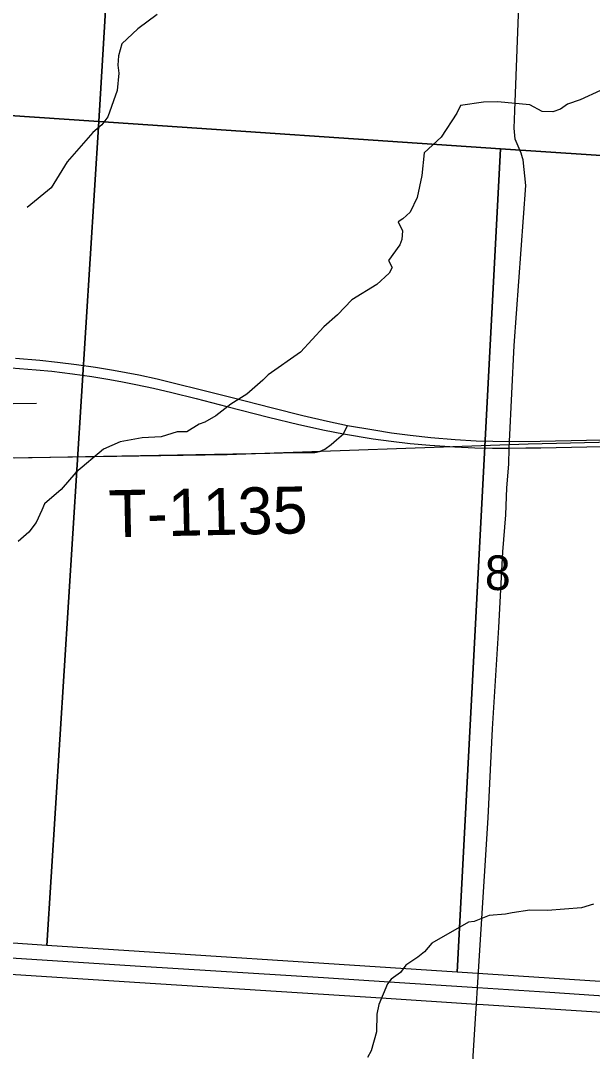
# Model space of a CAD drawing. Extents: x 0 to 34, y 0 to 22.
# Drawn here: x 6.134 to 6.826, y 16.537 to 17.784 of the extents above; entities that cross this region are included whole.
import ezdxf

# ---------------------------------------------------------------- set-up
doc = ezdxf.new("R2010")
doc.units = 0
for name, color, linetype in [('GM_X_Interstate_Route', 7, 'Continuous'), ('GM_X_Minor_River', 7, 'Continuous'), ('GM_X_Rail_Line', 7, 'Continuous'), ('GM_X_Section', 7, 'Continuous'), ('GM_X_Section_Text', 7, 'Continuous'), ('GM_X_Township_Road', 7, 'Continuous'), ('GM_X_Township_Road_Text', 7, 'Continuous'), ('GM_X_US_Route', 7, 'Continuous')]:
    doc.layers.add(name, color=color, linetype=linetype)

msp = doc.modelspace()

# ---------------------------------------------------------------- linework, layer by layer
at = {"layer": 'GM_X_Interstate_Route'}
msp.add_line((6.5803, 16.6216), (6.6872, 16.6147), dxfattribs=at)
for points in [[(3.3501, 16.8435), (3.6568, 16.822), (3.9185, 16.8032), (4.14, 16.7877), (4.3722, 16.7712), (4.604, 16.7548), (4.6996, 16.7473), (4.8669, 16.7351), (5.1594, 16.714), (5.3993, 16.6976), (5.5708, 16.6871), (5.7197, 16.6768), (5.8676, 16.668), (5.8733, 16.6677), (6.0223, 16.6571), (6.2793, 16.6405), (6.5008, 16.6267), (6.5803, 16.6216)], [(5.8539, 16.6483), (5.8694, 16.6473), (5.8755, 16.6469), (5.9988, 16.6386), (6.0215, 16.6374), (6.2785, 16.6207), (6.5705, 16.6021)], [(6.6872, 16.6147), (6.7745, 16.609), (6.9282, 16.5988), (7.1233, 16.586), (7.1966, 16.5814), (7.3203, 16.5739), (7.5541, 16.5599), (7.6369, 16.555), (7.7116, 16.5509), (7.763, 16.5476), (7.8179, 16.5444), (7.9309, 16.5375), (8.0934, 16.5278), (8.381, 16.5106), (8.5601, 16.5001), (8.6719, 16.4933), (8.7324, 16.4898), (8.7863, 16.4867), (8.8289, 16.4838), (8.9, 16.4798)], [(6.5705, 16.6021), (6.6858, 16.5947), (6.6939, 16.5942)], [(6.6939, 16.5942), (6.9254, 16.5792), (7.1337, 16.5658), (7.3189, 16.554), (7.5572, 16.54), (7.7106, 16.5304), (7.8168, 16.5243), (7.9297, 16.5174), (8.0923, 16.5078), (8.3775, 16.4913), (8.5578, 16.4804), (8.6708, 16.4732), (8.7313, 16.4698), (8.8282, 16.4636), (8.9, 16.4595)]]:
    msp.add_lwpolyline(points, dxfattribs=at)
at = {"layer": 'GM_X_Minor_River'}
for points in [[(6.2996, 17.7911), (6.2761, 17.7741), (6.2571, 17.7559), (6.2529, 17.7411), (6.2522, 17.7301), (6.2533, 17.7202), (6.2513, 17.6994), (6.2399, 17.6675), (6.2327, 17.6577), (6.2217, 17.6486), (6.1906, 17.613), (6.1716, 17.5815), (6.1424, 17.558)], [(6.836, 17.6992), (6.8114, 17.6879), (6.7962, 17.683), (6.7875, 17.6769), (6.7784, 17.6735), (6.7655, 17.6739), (6.7504, 17.6819), (6.7114, 17.6858), (6.6944, 17.6851), (6.6667, 17.6814), (6.6621, 17.6719), (6.6432, 17.6431), (6.6227, 17.6238), (6.62, 17.5964), (6.6142, 17.5699), (6.6055, 17.5524), (6.5968, 17.5441), (6.5911, 17.5407), (6.5963, 17.5297), (6.5956, 17.5191), (6.5933, 17.5126), (6.5796, 17.4937), (6.5838, 17.4853), (6.5803, 17.4785), (6.5655, 17.4648), (6.5352, 17.4463), (6.5178, 17.4281), (6.5011, 17.4134), (6.473, 17.3831), (6.4339, 17.3554), (6.4275, 17.349), (6.4081, 17.332), (6.3888, 17.3199), (6.3706, 17.3058), (6.3573, 17.2983), (6.3505, 17.296), (6.3357, 17.2866), (6.324, 17.2866), (6.3043, 17.2806), (6.2815, 17.2795), (6.255, 17.2746), (6.2346, 17.2655), (6.2012, 17.2375), (6.1837, 17.2167), (6.1632, 17.1996), (6.1602, 17.1917), (6.1533, 17.1769), (6.1446, 17.1651), (6.1317, 17.1542)], [(6.8276, 16.7153), (6.8128, 16.7111), (6.7719, 16.7078), (6.7503, 16.7082), (6.7291, 16.7049), (6.7211, 16.7034), (6.7011, 16.7019), (6.6833, 16.6947), (6.6761, 16.6936), (6.6321, 16.6683), (6.623, 16.658), (6.615, 16.6516), (6.6006, 16.6418), (6.5941, 16.633), (6.5828, 16.6247), (6.5782, 16.619), (6.5679, 16.594), (6.5653, 16.5826), (6.5648, 16.561), (6.5584, 16.5382), (6.5542, 16.5302)]]:
    msp.add_lwpolyline(points, dxfattribs=at)
at = {"layer": 'GM_X_Rail_Line'}
msp.add_lwpolyline([(2.1, 17.1885), (2.293, 17.1932), (3.2433, 17.211), (3.5049, 17.2168), (5.1641, 17.2441), (5.3961, 17.2441), (6.3843, 17.2591), (6.7484, 17.272), (7.243, 17.2836), (8.0477, 17.3015), (8.4974, 17.3184), (8.9, 17.3324)], dxfattribs=at)
at = {"layer": 'GM_X_Section'}
for points in [[(5.2662, 18.2926), (5.3729, 18.2854), (5.6268, 18.2675), (6.2624, 18.2212), (6.2291, 17.6617), (5.7501, 17.6941), (5.2271, 17.7305)], [(6.2624, 18.2212), (6.7545, 18.2014), (7.2638, 18.1848), (7.2905, 18.1831), (7.2571, 17.593), (6.7148, 17.6287), (6.2291, 17.6617)], [(5.7501, 17.6941), (6.2291, 17.6617), (6.166, 16.6655), (5.6796, 16.6989)], [(6.2291, 17.6617), (6.7148, 17.6287), (6.6627, 16.6332), (6.166, 16.6655)], [(6.7148, 17.6287), (7.2571, 17.593), (7.1941, 16.5986), (6.6627, 16.6332)]]:
    msp.add_lwpolyline(points, close=True, dxfattribs=at)
at = {"layer": 'GM_X_Township_Road'}
msp.add_line((6.1254, 17.3207), (6.1538, 17.3214), dxfattribs=at)
for points in [[(6.7254, 17.2668), (6.7258, 17.2749), (6.7316, 17.3909), (6.7455, 17.5846), (6.7423, 17.6154), (6.7415, 17.6181), (6.7401, 17.6235), (6.7327, 17.6404), (6.7315, 17.654), (6.7322, 17.6746), (6.7412, 17.9082), (6.7674, 18.2001)], [(6.1266, 17.255), (6.2346, 17.257), (6.4361, 17.261), (6.4664, 17.2617), (6.4833, 17.2617), (6.4902, 17.2617), (6.4962, 17.2628), (6.5025, 17.2658), (6.51, 17.2712), (6.5166, 17.2769), (6.5251, 17.2841), (6.5299, 17.2944)], [(6.702, 16.8613), (6.7053, 16.9273), (6.7129, 17.0499), (6.7178, 17.1415), (6.7213, 17.1863), (6.7228, 17.2189), (6.7249, 17.2474), (6.7254, 17.2668)], [(6.6851, 16.5838), (6.6858, 16.5947), (6.6872, 16.6147), (6.7, 16.82), (6.702, 16.8613)], [(6.6753, 16.4262), (6.6759, 16.4341), (6.6851, 16.5838)]]:
    msp.add_lwpolyline(points, dxfattribs=at)
at = {"layer": 'GM_X_US_Route'}
for p, q in [((6.7052, 17.267), (6.7254, 17.2668)), ((6.7254, 17.2668), (6.7455, 17.2671))]:
    msp.add_line(p, q, dxfattribs=at)
for points in [[(6.1281, 17.3756), (6.1577, 17.3733), (6.1791, 17.3709), (6.2021, 17.3682), (6.225, 17.365), (6.2469, 17.3613), (6.2623, 17.3585), (6.2776, 17.3554), (6.2996, 17.3507), (6.3222, 17.3452), (6.3517, 17.338), (6.3889, 17.3284), (6.4393, 17.3157), (6.4759, 17.3065), (6.5058, 17.2994), (6.5299, 17.2944), (6.5616, 17.2889), (6.5833, 17.2855), (6.6059, 17.2826), (6.6306, 17.2799), (6.6601, 17.2774), (6.6856, 17.2759), (6.7258, 17.2749)], [(5.8697, 17.3623), (6.0002, 17.365), (6.0394, 17.3655), (6.0709, 17.3656), (6.0987, 17.3652), (6.1232, 17.3641), (6.1531, 17.3616), (6.1723, 17.3599), (6.1974, 17.3568), (6.2205, 17.3534), (6.2422, 17.35), (6.2579, 17.3471), (6.274, 17.3438), (6.2953, 17.3394), (6.3173, 17.3342), (6.3469, 17.3269), (6.384, 17.3174), (6.4345, 17.3045), (6.4709, 17.2954), (6.502, 17.2885), (6.5251, 17.2841)], [(6.5251, 17.2841), (6.5611, 17.2782), (6.5827, 17.2753), (6.6055, 17.2726), (6.6295, 17.2704), (6.6596, 17.2683), (6.6839, 17.2672), (6.7052, 17.267)], [(6.7258, 17.2749), (6.7629, 17.2754), (6.8191, 17.2765), (6.8875, 17.2779)], [(6.7455, 17.2671), (6.7636, 17.2674), (6.8194, 17.2685), (6.8878, 17.2699)]]:
    msp.add_lwpolyline(points, dxfattribs=at)

# ---------------------------------------------------------------- texts
at = {"layer": 'GM_X_Section_Text'}
msp.add_text('8', height=0.0419, rotation=0, dxfattribs=at).set_placement((6.6961, 17.0953))
at = {"layer": 'GM_X_Township_Road_Text'}
msp.add_text('T-1135', height=0.05682, rotation=1.1694, dxfattribs=at).set_placement((6.2414, 17.1591))

doc.saveas('drawing.dxf')
